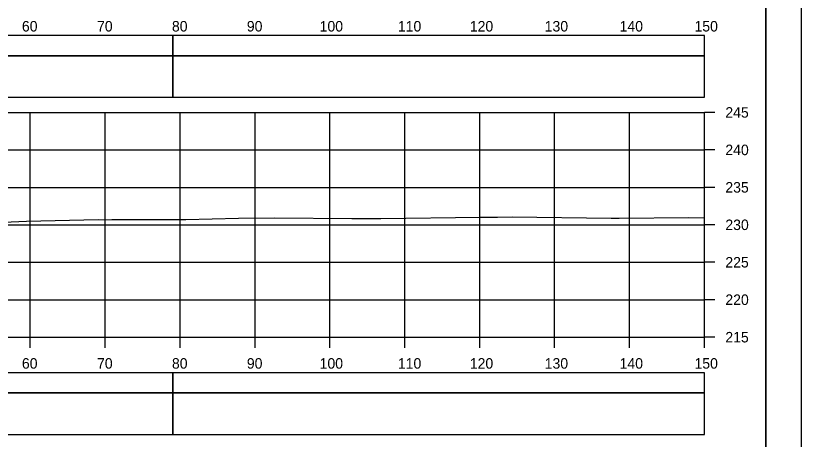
# Model space of a CAD drawing. Extents: x 1386544 to 1388153, y 379785 to 390999.
# Drawn here: x 1387417.7 to 1387522.6, y 385981.4 to 386037.9 of the extents above; entities that cross this region are included whole.
import ezdxf

# ---------------------------------------------------------------- set-up
doc = ezdxf.new("R2010")
doc.units = 0
for name, color, linetype in [('R_Axis', 7, 'Continuous'), ('R_Axis Annot', 7, 'Continuous'), ('R_Border', 7, 'Continuous'), ('R_Exist Surface', 7, 'Continuous'), ('R_Grid', 7, 'Continuous'), ('R_No Plot', 7, 'Continuous'), ('R_Striping', 7, 'Continuous')]:
    doc.layers.add(name, color=color, linetype=linetype)

msp = doc.modelspace()

# ---------------------------------------------------------------- linework, layer by layer
at = {"layer": 'R_Axis'}
for p, q in [((1387509.67, 385994.98), (1387509.67, 386024.98)), ((1387511.07, 386024.98), (1387509.67, 386024.98)), ((1387511.07, 386019.98), (1387509.67, 386019.98)), ((1387511.07, 386014.98), (1387509.67, 386014.98)), ((1387511.07, 386009.98), (1387509.67, 386009.98)), ((1387511.07, 386004.98), (1387509.67, 386004.98)), ((1387511.07, 385999.98), (1387509.67, 385999.98)), ((1387209.67, 385994.98), (1387509.67, 385994.98)), ((1387419.67, 385993.58), (1387419.67, 385994.98)), ((1387429.67, 385993.58), (1387429.67, 385994.98)), ((1387439.67, 385993.58), (1387439.67, 385994.98)), ((1387449.67, 385993.58), (1387449.67, 385994.98)), ((1387459.67, 385993.58), (1387459.67, 385994.98)), ((1387469.67, 385993.58), (1387469.67, 385994.98)), ((1387479.67, 385993.58), (1387479.67, 385994.98)), ((1387489.67, 385993.58), (1387489.67, 385994.98)), ((1387499.67, 385993.58), (1387499.67, 385994.98)), ((1387509.67, 385993.58), (1387509.67, 385994.98)), ((1387511.07, 385994.98), (1387509.67, 385994.98))]:
    msp.add_line(p, q, dxfattribs=at)
at = {"layer": 'R_Axis Annot'}
for points in [[(1387438.7, 386032.53), (1387509.68, 386032.53), (1387509.68, 386035.24), (1387438.7, 386035.24)], [(1387438.7, 386027.01), (1387509.68, 386027.01), (1387509.68, 386032.53), (1387438.7, 386032.53)], [(1387438.7, 385987.53), (1387509.68, 385987.53), (1387509.68, 385990.24), (1387438.7, 385990.24)], [(1387438.7, 385982.01), (1387509.68, 385982.01), (1387509.68, 385987.53), (1387438.7, 385987.53)]]:
    msp.add_lwpolyline(points, close=True, dxfattribs=at)
at = {"layer": 'R_Border'}
msp.add_line((1387517.86, 385882.81), (1387517.86, 386088.27), dxfattribs=at)
at = {"layer": 'R_Exist Surface'}
msp.add_lwpolyline([(1387411.98, 386010.15), (1387419.15, 386010.46), (1387428.72, 386010.67), (1387429.6, 386010.66), (1387430.57, 386010.67), (1387440.45, 386010.7), (1387447.48, 386010.85), (1387452.33, 386010.92), (1387462.59, 386010.83), (1387466.47, 386010.84), (1387479.78, 386011.01), (1387482.04, 386011.02), (1387483.99, 386011.03), (1387497.24, 386010.88), (1387498.3, 386010.88), (1387507.59, 386010.95), (1387509.67, 386010.92)], dxfattribs=at)
at = {"layer": 'R_Grid'}
for p, q in [((1387209.67, 386024.98), (1387509.67, 386024.98)), ((1387419.67, 385994.98), (1387419.67, 386024.98)), ((1387429.67, 385994.98), (1387429.67, 386024.98)), ((1387439.67, 385994.98), (1387439.67, 386024.98)), ((1387449.67, 385994.98), (1387449.67, 386024.98)), ((1387459.67, 385994.98), (1387459.67, 386024.98)), ((1387469.67, 385994.98), (1387469.67, 386024.98)), ((1387479.67, 385994.98), (1387479.67, 386024.98)), ((1387489.67, 385994.98), (1387489.67, 386024.98)), ((1387499.67, 385994.98), (1387499.67, 386024.98)), ((1387509.67, 385994.98), (1387509.67, 386024.98)), ((1387209.67, 386019.98), (1387509.67, 386019.98)), ((1387209.67, 386014.98), (1387509.67, 386014.98)), ((1387209.67, 386009.98), (1387509.67, 386009.98)), ((1387209.67, 386004.98), (1387509.67, 386004.98)), ((1387209.67, 385999.98), (1387509.67, 385999.98)), ((1387209.67, 385994.98), (1387509.67, 385994.98))]:
    msp.add_line(p, q, dxfattribs=at)
at = {"layer": 'R_No Plot'}
for points in [[(1387189.27, 386092.17), (1387522.61, 386092.17), (1387522.61, 385878.83), (1387189.27, 385878.83)], [(1387435.6, 386088.27), (1387455.22, 386088.27), (1387455.22, 386078.39), (1387471.33, 386078.39), (1387494.53, 386078.39), (1387494.53, 386054.06), (1387517.86, 386054.06), (1387517.86, 385882.81), (1387201.68, 385882.81), (1387201.68, 386088.27)]]:
    msp.add_lwpolyline(points, close=True, dxfattribs=at)
at = {"layer": 'R_Striping'}
for points in [[(1387407.36, 386032.54), (1387438.7, 386032.54), (1387438.7, 386035.24), (1387407.36, 386035.24)], [(1387407.36, 386027.01), (1387438.7, 386027.01), (1387438.7, 386032.54), (1387407.36, 386032.54)], [(1387407.36, 385987.54), (1387438.7, 385987.54), (1387438.7, 385990.24), (1387407.36, 385990.24)], [(1387407.36, 385982.01), (1387438.7, 385982.01), (1387438.7, 385987.54), (1387407.36, 385987.54)]]:
    msp.add_lwpolyline(points, close=True, dxfattribs=at)

# ---------------------------------------------------------------- texts
at = {"layer": 'R_Axis Annot'}
for s, p in [('60', (1387418.55, 386035.78)), ('70', (1387428.58, 386035.78)), ('80', (1387438.58, 386035.78)), ('90', (1387448.58, 386035.78)), ('100', (1387458.3, 386035.78)), ('110', (1387468.75, 386035.78)), ('120', (1387478.35, 386035.78)), ('130', (1387488.35, 386035.78)), ('140', (1387498.35, 386035.78)), ('150', (1387508.35, 386035.78)), ('245', (1387512.47, 386024.28)), ('240', (1387512.47, 386019.28)), ('235', (1387512.47, 386014.28)), ('230', (1387512.47, 386009.28)), ('225', (1387512.47, 386004.28)), ('220', (1387512.47, 385999.28)), ('215', (1387512.47, 385994.28)), ('60', (1387418.55, 385990.78)), ('70', (1387428.58, 385990.78)), ('80', (1387438.58, 385990.78)), ('90', (1387448.58, 385990.78)), ('100', (1387458.3, 385990.78)), ('110', (1387468.75, 385990.78)), ('120', (1387478.35, 385990.78)), ('130', (1387488.35, 385990.78)), ('140', (1387498.35, 385990.78)), ('150', (1387508.35, 385990.78))]:
    msp.add_text(s, height=1.4, dxfattribs=at).set_placement(p)

doc.saveas('drawing.dxf')
